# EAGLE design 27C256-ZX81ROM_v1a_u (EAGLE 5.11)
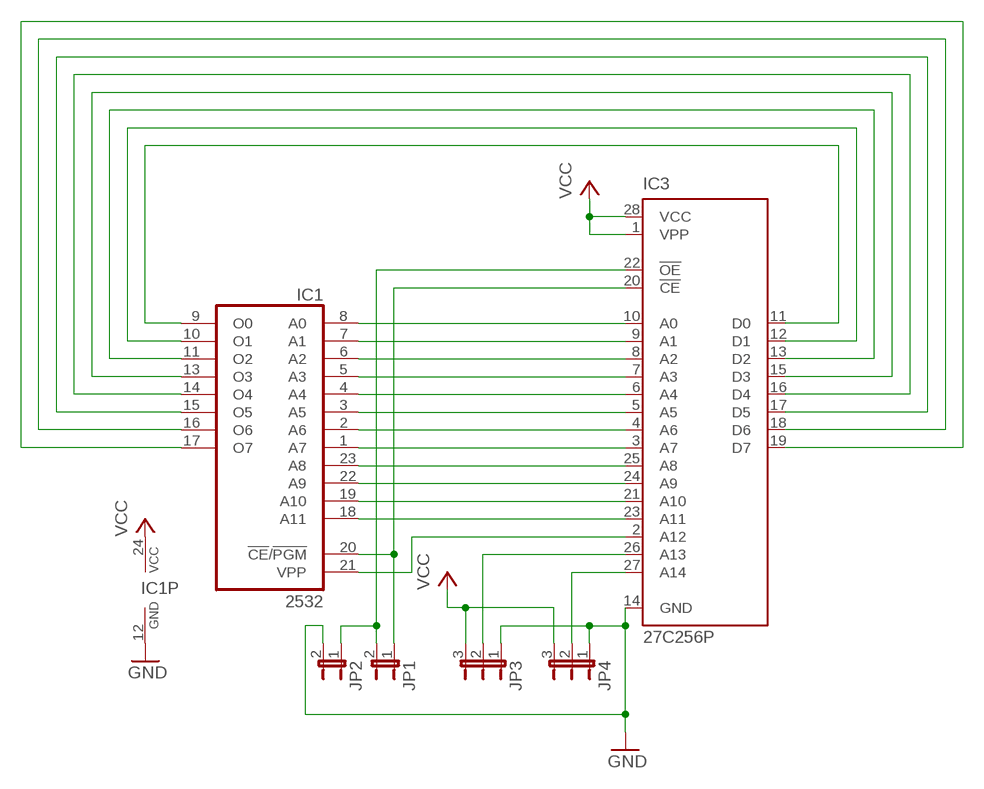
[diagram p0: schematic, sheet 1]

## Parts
IC1  2532  [DIL24]
IC3  27C256P  [DIL28-6]
JP1  JP1E  [JP1]
JP2  JP1E  [JP1]
JP3  JP2E  [JP2]
JP4  JP2E  [JP2]

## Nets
GND [power]: IC1.12(GND) IC3.14(GND) JP2.2 JP3.1 JP4.1
N$1: IC1.8(A0) IC3.10(A0)
N$2: IC1.7(A1) IC3.9(A1)
N$3: IC1.6(A2) IC3.8(A2)
N$4: IC1.5(A3) IC3.7(A3)
N$5: IC1.4(A4) IC3.6(A4)
N$6: IC1.3(A5) IC3.5(A5)
N$7: IC1.2(A6) IC3.4(A6)
N$8: IC1.1(A7) IC3.3(A7)
N$9: IC1.23(A8) IC3.25(A8)
N$10: IC1.22(A9) IC3.24(A9)
N$11: IC1.19(A10) IC3.21(A10)
N$12: IC1.18(A11) IC3.23(A11)
N$13: IC3.22(!OE) JP1.2 JP2.1
N$14: IC1.20(!CE!/!PGM) IC3.20(!CE) JP1.1
N$15: IC1.9(O0) IC3.11(D0)
N$16: IC1.10(O1) IC3.12(D1)
N$17: IC1.11(O2) IC3.13(D2)
N$18: IC1.13(O3) IC3.15(D3)
N$19: IC1.14(O4) IC3.16(D4)
N$20: IC1.15(O5) IC3.17(D5)
N$21: IC1.16(O6) IC3.18(D6)
N$22: IC1.17(O7) IC3.19(D7)
N$23: IC1.21(VPP) IC3.2(A12)
N$25: IC3.26(A13) JP3.2
N$26: IC3.27(A14) JP4.2
VCC [power]: IC1.24(VCC) IC3.1(VPP) IC3.28(VCC) JP3.3 JP4.3

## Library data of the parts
IC1 = GIMEchip:2532: MEMORY
IC3 = microchip:27*256: CMOS EPROM 256 K (32 K x 8), low voltage; MF: Arrow Electronics; MPN: M27C256B15F1; OC_FARNELL: 1125431; OC_NEWARK: 93K7335
JP1 JP2 = jumper:JP1E: JUMPER
JP3 JP4 = jumper:JP2E: JUMPER

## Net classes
0 default: width 0.203 mm, clearance 0.203 mm
1 power: width 0.406 mm, clearance 0.254 mm

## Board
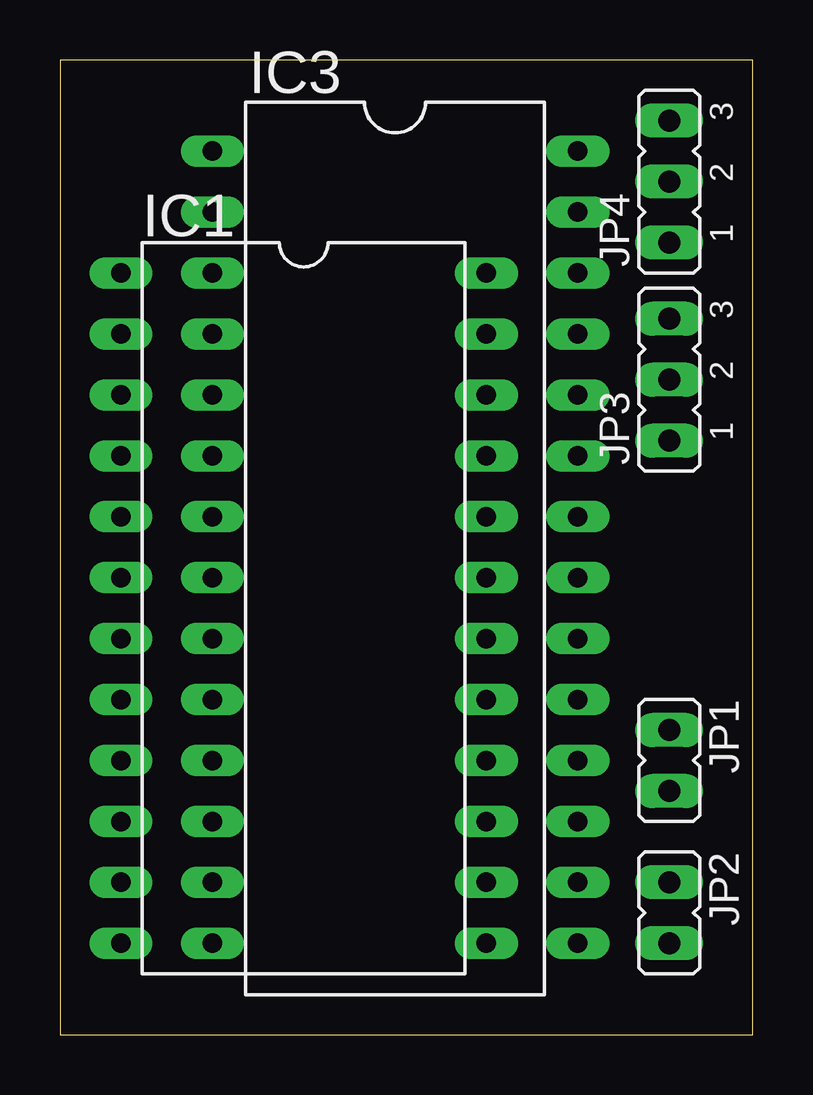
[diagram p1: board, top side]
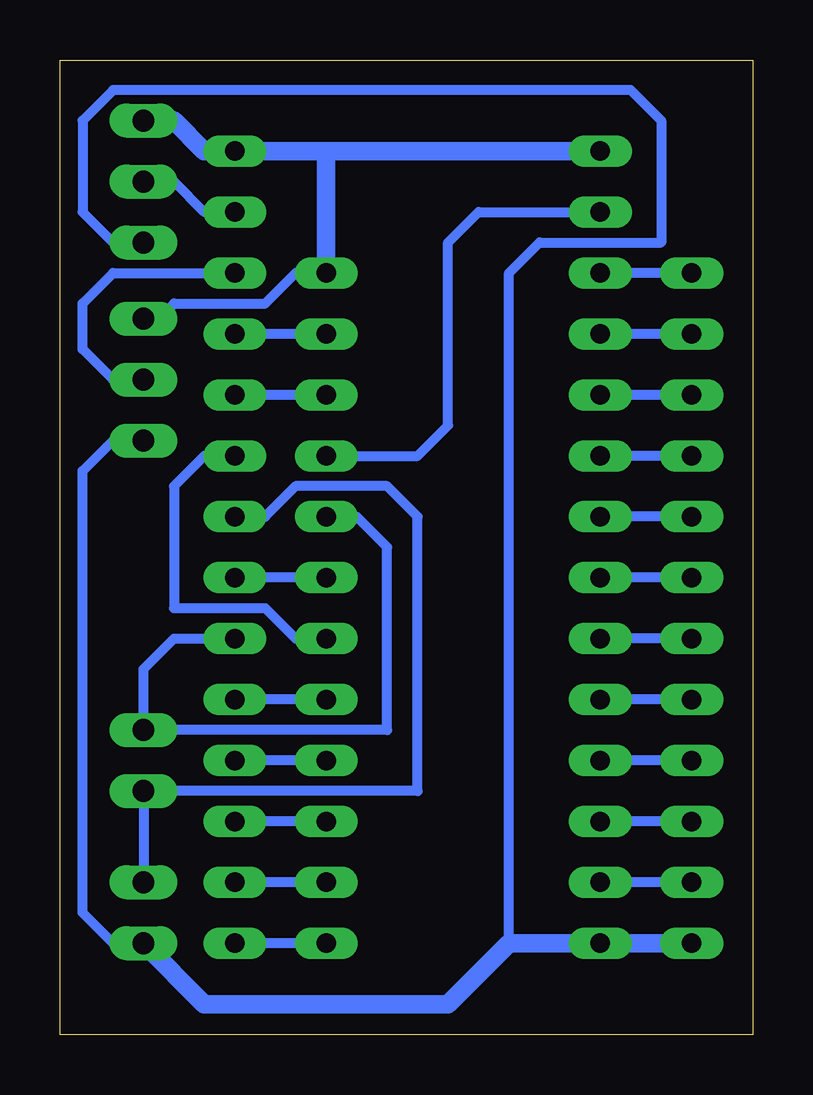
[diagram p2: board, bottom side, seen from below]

Size 28.88 x 40.63 mm. Coordinates in mm from the lower left corner, seen from the top.
Outline: 0,0 28.88,0 28.88,40.63 0,40.63 0,0
Copper layers (1*16): Top 0.035mm / dielectric 1.5mm / Bottom 0.035mm
Design rules "trida4_12.5mil": minimum track width 12.5mil, minimum drill 0.8mm, track to track 12.5mil, track to pad 12.5mil, pad to pad 12.5mil, via to via 12.5mil, smd to smd 8mil, copper to edge 0.1mm, drill to drill 1.25mm, minimum pad ring 10mil, minimum via ring 8mil, stop-mask expansion 4mil, vias tented up to drill 0mil, thermal gap 10mil

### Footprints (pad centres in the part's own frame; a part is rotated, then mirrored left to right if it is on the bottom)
DIL24 = drill 0.813 long: 1 -13.97,-7.62; 2 -11.43,-7.62; 3 -8.89,-7.62; 4 -6.35,-7.62; 5 -3.81,-7.62; 6 -1.27,-7.62; 7 1.27,-7.62; 8 3.81,-7.62; 9 6.35,-7.62; 10 8.89,-7.62; 11 11.43,-7.62; 12 13.97,-7.62; 13 13.97,7.62; 14 11.43,7.62; 15 8.89,7.62; 16 6.35,7.62; 17 3.81,7.62; 18 1.27,7.62; 19 -1.27,7.62; 20 -3.81,7.62; 21 -6.35,7.62; 22 -8.89,7.62; 23 -11.43,7.62; 24 -13.97,7.62
DIL28-6 = drill 0.813 long: 1 -16.51,-7.62; 2 -13.97,-7.62; 3 -11.43,-7.62; 4 -8.89,-7.62; 5 -6.35,-7.62; 6 -3.81,-7.62; 7 -1.27,-7.62; 8 1.27,-7.62; 9 3.81,-7.62; 10 6.35,-7.62; 11 8.89,-7.62; 12 11.43,-7.62; 13 13.97,-7.62; 14 16.51,-7.62; 15 16.51,7.62; 16 13.97,7.62; 17 11.43,7.62; 18 8.89,7.62; 19 6.35,7.62; 20 3.81,7.62; 21 1.27,7.62; 22 -1.27,7.62; 23 -3.81,7.62; 24 -6.35,7.62; 25 -8.89,7.62; 26 -11.43,7.62; 27 -13.97,7.62; 28 -16.51,7.62
JP1 = drill 0.914 long: 1 0,-1.27; 2 0,1.27
JP2 = drill 0.914 long: 1 -2.54,0; 2 0,0; 3 2.54,0

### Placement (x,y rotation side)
IC1  10.16,17.78 270 top
IC3  13.97,20.32 270 top
JP1  25.4,11.43 180 top
JP2  25.4,5.08 180 top
JP3  25.4,27.3 90 top
JP4  25.4,35.56 90 top

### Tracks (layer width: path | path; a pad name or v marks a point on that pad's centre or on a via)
GND
  Bottom 0.406: JP3.1 26.67,24.77 27.94,23.5 27.94,5.08 26.67,3.81 JP2.2 | JP4.1 26.67,33.02 27.94,34.29 27.94,38.1 26.67,39.37 5.08,39.37 3.81,38.1 3.81,33.02 8.89,33.02 10.16,31.75 10.16,3.81
  Bottom 0.762: IC1.12 IC3.14 10.16,3.81 12.7,1.27 22.86,1.27 JP2.2
N$1
  Bottom 0.406: IC1.8 IC3.10
N$2
  Bottom 0.406: IC1.7 IC3.9
N$3
  Bottom 0.406: IC1.6 IC3.8
N$4
  Bottom 0.406: IC1.5 IC3.7
N$5
  Bottom 0.406: IC1.4 IC3.6
N$6
  Bottom 0.406: IC1.3 IC3.5
N$7
  Bottom 0.406: IC1.2 IC3.4
N$8
  Bottom 0.406: IC1.1 IC3.3
N$9
  Bottom 0.406: IC1.23 IC3.25
N$10
  Bottom 0.406: IC1.22 IC3.24
N$11
  Bottom 0.406: IC1.19 IC3.21
N$12
  Bottom 0.406: IC3.23 22.86,24.13 24.13,22.86 24.13,17.78 20.32,17.78 19.05,16.51 IC1.18
N$13
  Bottom 0.406: IC3.22 20.32,21.59 19.05,22.86 15.24,22.86 13.97,21.59 13.97,10.16 JP1.2 JP2.1
N$14
  Bottom 0.406: IC3.20 24.13,16.51 25.4,15.24 JP1.1 15.24,12.7 15.24,20.32 16.51,21.59 IC1.20
N$15
  Bottom 0.406: IC1.9 IC3.11
N$16
  Bottom 0.406: IC1.10 IC3.12
N$17
  Bottom 0.406: IC1.11 IC3.13
N$18
  Bottom 0.406: IC1.13 IC3.15
N$19
  Bottom 0.406: IC1.14 IC3.16
N$20
  Bottom 0.406: IC1.15 IC3.17
N$21
  Bottom 0.406: IC1.16 IC3.18
N$22
  Bottom 0.406: IC1.17 IC3.19
N$23
  Bottom 0.406: IC1.21 13.97,24.13 12.7,25.4 12.7,33.02 11.43,34.29 IC3.2
N$25
  Bottom 0.406: JP3.2 26.67,27.3 27.94,28.57 27.94,30.48 26.67,31.75 IC3.26
N$26
  Bottom 0.406: IC3.27 22.86,34.29 24.13,35.56 JP4.2
VCC
  Bottom 0.406: JP3.3 24.77,29.84 24.13,30.48 20.32,30.48 19.05,31.75 IC1.24
  Bottom 0.762: 17.78,36.83 IC1.24 | 17.78,36.83 IC3.28 22.86,36.83 24.13,38.1 JP4.3 | IC3.1 17.78,36.83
